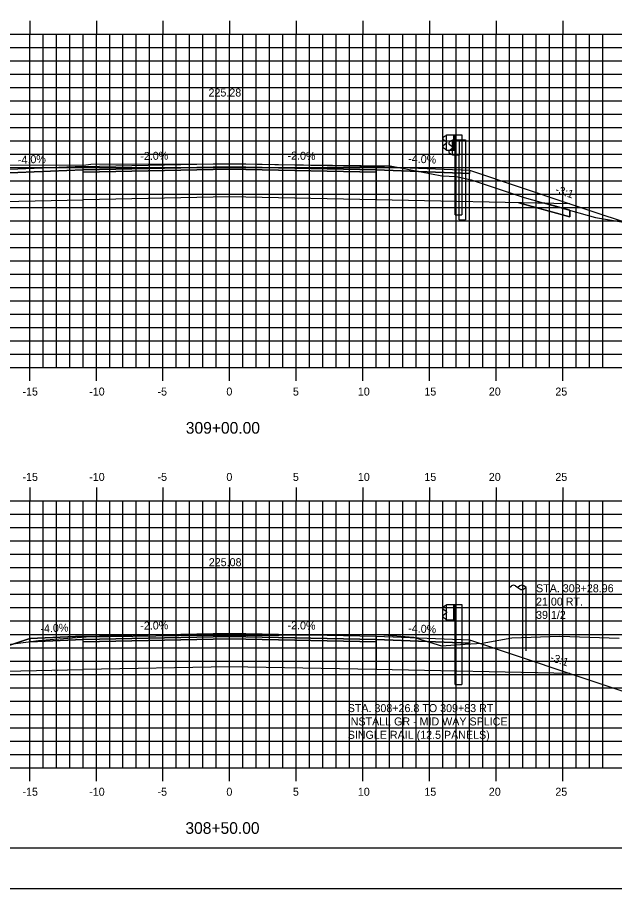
# Model space of a CAD drawing. Extents: x 1137876 to 1138046, y 608981 to 609091.
# Drawn here: x 1137943.2 to 1137988.1, y 608981.3 to 609046.6 of the extents above; entities that cross this region are included whole.
import ezdxf

# ---------------------------------------------------------------- set-up
doc = ezdxf.new("R2010")
doc.units = 0
for name, color, linetype in [('ANNOTATION', 7, 'Continuous'), ('BORDER', 7, 'Continuous'), ('D_Guardrail_Beam_Lt', 7, 'Continuous'), ('D_Guardrail_Beam_Rt', 7, 'Continuous'), ('D_Roadway_Centerline', 7, 'Continuous'), ('D_Roadway_Centerline_Text', 7, 'Continuous'), ('D_Roadway_Edge_Shoulder', 7, 'Continuous'), ('D_Roadway_Edge_TW', 7, 'Continuous'), ('D_Roadway_Pavement', 7, 'Continuous'), ('D_Roadway_SlopeLines', 7, 'Continuous'), ('D_Roadway_SubGrade', 7, 'Continuous'), ('D_Text_Standard', 7, 'Continuous'), ('D_Utilities_Pole_Joint_Rt', 7, 'Continuous'), ('H_V ANNOTATION', 7, 'Continuous'), ('MAJOR', 7, 'Continuous'), ('MINOR', 7, 'Continuous'), ('PLOT BOUNDARY', 7, 'Continuous'), ('S_Guardrail_Beam', 7, 'Continuous'), ('S_Roadway_Centerline', 7, 'Continuous'), ('SHADING', 7, 'Continuous')]:
    doc.layers.add(name, color=color, linetype=linetype)

msp = doc.modelspace()

# ---------------------------------------------------------------- linework, layer by layer
msp.add_lwpolyline([(1137920.838, 609001.638), (1137922.088, 609001.503), (1137923.338, 609001.228), (1137924.588, 609000.813), (1137925.838, 609000.258), (1137933.441, 608996.457), (1137936.441, 608997.457), (1137944.165, 609000.031), (1137944.166, 609000.031), (1137948.166, 609000.191), (1137959.166, 609000.411), (1137970.166, 609000.191), (1137977.166, 608999.911), (1137984.698, 608997.4), (1137989.882, 608995.673), (1137996.551, 608999.007), (1137997.801, 608999.558), (1137999.051, 608999.962), (1138000.301, 609000.217), (1138001.551, 609000.325)])
at = {"layer": 'BORDER'}
msp.add_lwpolyline([(1137884.166, 608984.335), (1138044.166, 608984.335), (1138044.166, 609089.335), (1137884.166, 609089.335)], close=True, dxfattribs=at)
at = {"layer": 'D_Guardrail_Beam_Lt'}
for p, q in [((1137975.347, 609037.679), (1137975.203, 609037.579)), ((1137975.437, 609037.7), (1137975.363, 609037.685)), ((1137975.203, 609037.436), (1137975.399, 609037.3)), ((1137975.399, 609037.101), (1137975.203, 609036.964)), ((1137975.203, 609036.821), (1137975.347, 609036.721)), ((1137975.432, 609037.235), (1137975.432, 609037.165)), ((1137975.363, 609036.715), (1137975.437, 609036.7)), ((1137975.347, 609002.47), (1137975.203, 609002.37)), ((1137975.203, 609002.227), (1137975.399, 609002.091)), ((1137975.437, 609002.491), (1137975.363, 609002.477)), ((1137975.399, 609001.892), (1137975.203, 609001.755)), ((1137975.203, 609001.612), (1137975.347, 609001.512)), ((1137975.432, 609002.026), (1137975.432, 609001.956)), ((1137975.363, 609001.506), (1137975.437, 609001.491))]:
    msp.add_line(p, q, dxfattribs=at)
for centre, major_axis, start_param, end_param in [((1137975.254, 609037.507), (-0.0877, 0), 5.323254, 7.243116), ((1137975.371, 609037.645), (-0.0417, 0), 4.907132, 5.323254), ((1137975.254, 609036.893), (-0.0877, 0), 5.323254, 7.243116), ((1137975.353, 609037.235), (0.0789, 0), 0, 0.959931), ((1137975.353, 609037.165), (0.0789, 0), 5.323254, 6.283185), ((1137975.371, 609036.755), (-0.0417, 0), 0.959931, 1.376053), ((1137975.254, 609002.298), (-0.0877, 0), 5.323254, 7.243116), ((1137975.371, 609002.436), (-0.0417, 0), 4.907132, 5.323254), ((1137975.254, 609001.684), (-0.0877, 0), 5.323254, 7.243116), ((1137975.353, 609002.026), (0.0789, 0), 0, 0.959931), ((1137975.353, 609001.956), (0.0789, 0), 5.323254, 6.283185), ((1137975.371, 609001.546), (-0.0417, 0), 0.959931, 1.376053)]:
    msp.add_ellipse(centre, major_axis=major_axis, ratio=0.995501, start_param=start_param, end_param=end_param, dxfattribs=at)
at = {"layer": 'D_Guardrail_Beam_Rt'}
for p, q in [((1137975.437, 609037.783), (1137976.124, 609037.783)), ((1137975.437, 609036.617), (1137975.437, 609037.783)), ((1137975.958, 609037.783), (1137975.958, 609036.617)), ((1137976.062, 609037.783), (1137976.062, 609036.617)), ((1137976.124, 609037.783), (1137976.595, 609037.783)), ((1137976.124, 609037.783), (1137976.124, 609036.617)), ((1137976.595, 609037.783), (1137976.595, 609031.783)), ((1137976.124, 609036.617), (1137975.437, 609036.617)), ((1137976.103, 609031.783), (1137976.103, 609036.617)), ((1137976.103, 609031.783), (1137976.595, 609031.783)), ((1137975.437, 609002.574), (1137976.124, 609002.574)), ((1137975.437, 609001.408), (1137975.437, 609002.574)), ((1137975.958, 609002.574), (1137975.958, 609001.408)), ((1137976.062, 609002.574), (1137976.062, 609001.408)), ((1137976.124, 609002.574), (1137976.595, 609002.574)), ((1137976.124, 609002.574), (1137976.124, 609001.408)), ((1137976.595, 609002.574), (1137976.595, 608996.574)), ((1137976.124, 609001.408), (1137975.437, 609001.408)), ((1137976.103, 608996.574), (1137976.103, 609001.408)), ((1137976.103, 608996.574), (1137976.595, 608996.574))]:
    msp.add_line(p, q, dxfattribs=at)
at = {"layer": 'D_Roadway_Edge_Shoulder'}
for points in [[(1137948.166, 609035.4), (1137940.788, 609035.105), (1137940.788, 609034.855), (1137948.166, 609035.15)], [(1137970.166, 609035.4), (1137977.166, 609035.12), (1137977.166, 609034.87), (1137970.166, 609035.15)], [(1137948.166, 609000.191), (1137944.166, 609000.031), (1137944.166, 608999.781), (1137948.166, 608999.941)], [(1137970.166, 609000.191), (1137977.166, 608999.911), (1137977.166, 608999.661), (1137970.166, 608999.941)]]:
    msp.add_lwpolyline(points, close=True, dxfattribs=at)
at = {"layer": 'D_Roadway_Edge_TW'}
for points in [[(1137948.166, 609035.15), (1137948.166, 609035.4), (1137959.166, 609035.62), (1137970.166, 609035.4), (1137970.166, 609035.15), (1137959.166, 609035.37)], [(1137948.166, 608999.941), (1137948.166, 609000.191), (1137959.166, 609000.411), (1137970.166, 609000.191), (1137970.166, 608999.941), (1137959.166, 609000.161)]]:
    msp.add_lwpolyline(points, close=True, dxfattribs=at)
at = {"layer": 'D_Roadway_Pavement'}
for points in [[(1137948.166, 609034.983), (1137948.166, 609035.15), (1137959.166, 609035.37), (1137970.166, 609035.15), (1137970.166, 609034.983), (1137959.166, 609035.203)], [(1137948.166, 608999.774), (1137948.166, 608999.941), (1137959.166, 609000.161), (1137970.166, 608999.941), (1137970.166, 608999.774), (1137959.166, 608999.994)]]:
    msp.add_lwpolyline(points, close=True, dxfattribs=at)
at = {"layer": 'D_Roadway_SlopeLines'}
for points in [[(1137984.698, 609032.125), (1137984.698, 609031.625), (1137980.875, 609032.686)], [(1137984.698, 609032.609), (1137990.642, 609030.628)], [(1137984.698, 608997.4), (1137989.882, 608995.673)]]:
    msp.add_lwpolyline(points, dxfattribs=at)
at = {"layer": 'D_Roadway_SubGrade'}
msp.add_lwpolyline([(1137939.722, 609032.731), (1137948.166, 609032.9), (1137948.166, 609034.983), (1137948.166, 609035.15), (1137940.788, 609034.855), (1137940.788, 609035.105), (1137940.787, 609035.105), (1137940.787, 609035.105)], dxfattribs=at)
for points in [[(1137948.166, 609032.9), (1137948.166, 609034.983), (1137959.166, 609035.203), (1137970.166, 609034.983), (1137970.166, 609032.9), (1137959.166, 609033.12)], [(1137970.166, 609034.983), (1137970.166, 609035.15), (1137977.166, 609034.87), (1137977.166, 609035.12), (1137977.166, 609035.12), (1137984.698, 609032.609), (1137970.166, 609032.9)], [(1137948.166, 608999.774), (1137948.166, 608999.941), (1137944.166, 608999.781), (1137944.166, 609000.031), (1137944.165, 609000.031), (1137936.441, 608997.457), (1137948.166, 608997.691)], [(1137948.166, 608997.691), (1137948.166, 608999.774), (1137959.166, 608999.994), (1137970.166, 608999.774), (1137970.166, 608997.691), (1137959.166, 608997.911)], [(1137970.166, 608999.774), (1137970.166, 608999.941), (1137977.166, 608999.661), (1137977.166, 608999.911), (1137977.166, 608999.911), (1137984.698, 608997.4), (1137970.166, 608997.691)]]:
    msp.add_lwpolyline(points, close=True, dxfattribs=at)
at = {"layer": 'D_Utilities_Pole_Joint_Rt'}
for p, q in [((1137980.164, 609003.85), (1137980.32, 609003.961)), ((1137980.164, 608999.092), (1137980.164, 609003.85)), ((1137980.632, 609003.961), (1137980.789, 609003.85)), ((1137980.945, 609003.961), (1137980.789, 609003.85)), ((1137980.789, 609003.85), (1137980.945, 609003.739)), ((1137981.414, 609003.85), (1137981.258, 609003.961)), ((1137981.258, 609003.739), (1137981.414, 609003.85)), ((1137981.414, 608999.092), (1137981.414, 609003.85))]:
    msp.add_line(p, q, dxfattribs=at)
for centre, start, end in [((1137980.476, 609003.74), 90, 125.26439), ((1137980.476, 609003.74), 54.73561, 90), ((1137981.101, 609003.74), 90, 125.26439), ((1137981.101, 609003.961), 234.73561, 270), ((1137981.101, 609003.74), 54.73561, 90), ((1137981.101, 609003.961), 270, 305.26439)]:
    msp.add_arc(centre, 0.271, start, end, dxfattribs=at)
at = {"layer": 'MAJOR'}
for p, q in [((1137944.166, 609046.337), (1137944.166, 609045.335)), ((1137949.166, 609046.337), (1137949.166, 609045.335)), ((1137954.166, 609046.337), (1137954.166, 609045.335)), ((1137959.166, 609046.337), (1137959.166, 609045.335)), ((1137964.166, 609046.337), (1137964.166, 609045.335)), ((1137969.166, 609046.337), (1137969.166, 609045.335)), ((1137974.166, 609046.337), (1137974.166, 609045.335)), ((1137979.166, 609046.337), (1137979.166, 609045.335)), ((1137984.166, 609046.337), (1137984.166, 609045.335)), ((1137889.166, 609045.335), (1138029.166, 609045.335)), ((1137889.166, 609045.335), (1138029.166, 609045.335)), ((1137944.166, 609020.335), (1137944.166, 609045.335)), ((1137949.166, 609020.335), (1137949.166, 609045.335)), ((1137954.166, 609020.335), (1137954.166, 609045.335)), ((1137959.166, 609020.335), (1137959.166, 609045.335)), ((1137964.166, 609020.335), (1137964.166, 609045.335)), ((1137969.166, 609020.335), (1137969.166, 609045.335)), ((1137974.166, 609020.335), (1137974.166, 609045.335)), ((1137979.166, 609020.335), (1137979.166, 609045.335)), ((1137984.166, 609020.335), (1137984.166, 609045.335)), ((1137889.166, 609040.335), (1138029.166, 609040.335)), ((1137889.166, 609035.335), (1138029.166, 609035.335)), ((1137889.166, 609030.335), (1138029.166, 609030.335)), ((1137889.166, 609025.335), (1138029.166, 609025.335)), ((1137889.166, 609020.335), (1138029.166, 609020.335)), ((1137889.166, 609020.335), (1138029.166, 609020.335)), ((1137944.166, 609019.333), (1137944.166, 609020.335)), ((1137949.166, 609019.333), (1137949.166, 609020.335)), ((1137954.166, 609019.333), (1137954.166, 609020.335)), ((1137959.166, 609019.333), (1137959.166, 609020.335)), ((1137964.166, 609019.333), (1137964.166, 609020.335)), ((1137969.166, 609019.333), (1137969.166, 609020.335)), ((1137974.166, 609019.333), (1137974.166, 609020.335)), ((1137979.166, 609019.333), (1137979.166, 609020.335)), ((1137984.166, 609019.333), (1137984.166, 609020.335)), ((1137944.166, 609011.337), (1137944.166, 609010.335)), ((1137949.166, 609011.337), (1137949.166, 609010.335)), ((1137954.166, 609011.337), (1137954.166, 609010.335)), ((1137959.166, 609011.337), (1137959.166, 609010.335)), ((1137964.166, 609011.337), (1137964.166, 609010.335)), ((1137969.166, 609011.337), (1137969.166, 609010.335)), ((1137974.166, 609011.337), (1137974.166, 609010.335)), ((1137979.166, 609011.337), (1137979.166, 609010.335)), ((1137984.166, 609011.337), (1137984.166, 609010.335)), ((1137889.166, 609010.335), (1138029.166, 609010.335)), ((1137889.166, 609010.335), (1138029.166, 609010.335)), ((1137944.166, 608990.335), (1137944.166, 609010.335)), ((1137949.166, 608990.335), (1137949.166, 609010.335)), ((1137954.166, 608990.335), (1137954.166, 609010.335)), ((1137959.166, 608990.335), (1137959.166, 609010.335)), ((1137964.166, 608990.335), (1137964.166, 609010.335)), ((1137969.166, 608990.335), (1137969.166, 609010.335)), ((1137974.166, 608990.335), (1137974.166, 609010.335)), ((1137979.166, 608990.335), (1137979.166, 609010.335)), ((1137984.166, 608990.335), (1137984.166, 609010.335)), ((1137889.166, 609005.335), (1138029.166, 609005.335)), ((1137889.166, 609000.335), (1138029.166, 609000.335)), ((1137889.166, 608995.335), (1138029.166, 608995.335)), ((1137889.166, 608990.335), (1138029.166, 608990.335)), ((1137889.166, 608990.335), (1138029.166, 608990.335)), ((1137944.166, 608989.333), (1137944.166, 608990.335)), ((1137949.166, 608989.333), (1137949.166, 608990.335)), ((1137954.166, 608989.333), (1137954.166, 608990.335)), ((1137959.166, 608989.333), (1137959.166, 608990.335)), ((1137964.166, 608989.333), (1137964.166, 608990.335)), ((1137969.166, 608989.333), (1137969.166, 608990.335)), ((1137974.166, 608989.333), (1137974.166, 608990.335)), ((1137979.166, 608989.333), (1137979.166, 608990.335)), ((1137984.166, 608989.333), (1137984.166, 608990.335))]:
    msp.add_line(p, q, dxfattribs=at)
at = {"layer": 'MINOR'}
for p, q in [((1137945.166, 609020.335), (1137945.166, 609045.335)), ((1137946.166, 609020.335), (1137946.166, 609045.335)), ((1137947.166, 609020.335), (1137947.166, 609045.335)), ((1137948.166, 609020.335), (1137948.166, 609045.335)), ((1137950.166, 609020.335), (1137950.166, 609045.335)), ((1137951.166, 609020.335), (1137951.166, 609045.335)), ((1137952.166, 609020.335), (1137952.166, 609045.335)), ((1137953.166, 609020.335), (1137953.166, 609045.335)), ((1137955.166, 609020.335), (1137955.166, 609045.335)), ((1137956.166, 609020.335), (1137956.166, 609045.335)), ((1137957.166, 609020.335), (1137957.166, 609045.335)), ((1137958.166, 609020.335), (1137958.166, 609045.335)), ((1137960.166, 609020.335), (1137960.166, 609045.335)), ((1137961.166, 609020.335), (1137961.166, 609045.335)), ((1137962.166, 609020.335), (1137962.166, 609045.335)), ((1137963.166, 609020.335), (1137963.166, 609045.335)), ((1137965.166, 609020.335), (1137965.166, 609045.335)), ((1137966.166, 609020.335), (1137966.166, 609045.335)), ((1137967.166, 609020.335), (1137967.166, 609045.335)), ((1137968.166, 609020.335), (1137968.166, 609045.335)), ((1137970.166, 609020.335), (1137970.166, 609045.335)), ((1137971.166, 609020.335), (1137971.166, 609045.335)), ((1137972.166, 609020.335), (1137972.166, 609045.335)), ((1137973.166, 609020.335), (1137973.166, 609045.335)), ((1137975.166, 609020.335), (1137975.166, 609045.335)), ((1137976.166, 609020.335), (1137976.166, 609045.335)), ((1137977.166, 609020.335), (1137977.166, 609045.335)), ((1137978.166, 609020.335), (1137978.166, 609045.335)), ((1137980.166, 609020.335), (1137980.166, 609045.335)), ((1137981.166, 609020.335), (1137981.166, 609045.335)), ((1137982.166, 609020.335), (1137982.166, 609045.335)), ((1137983.166, 609020.335), (1137983.166, 609045.335)), ((1137985.166, 609020.335), (1137985.166, 609045.335)), ((1137986.166, 609020.335), (1137986.166, 609045.335)), ((1137987.166, 609020.335), (1137987.166, 609045.335)), ((1137889.166, 609044.335), (1138029.166, 609044.335)), ((1137889.166, 609043.335), (1138029.166, 609043.335)), ((1137889.166, 609042.335), (1138029.166, 609042.335)), ((1137889.166, 609041.335), (1138029.166, 609041.335)), ((1137889.166, 609039.335), (1138029.166, 609039.335)), ((1137889.166, 609038.335), (1138029.166, 609038.335)), ((1137889.166, 609037.335), (1138029.166, 609037.335)), ((1137889.166, 609036.335), (1138029.166, 609036.335)), ((1137889.166, 609034.335), (1138029.166, 609034.335)), ((1137889.166, 609033.335), (1138029.166, 609033.335)), ((1137889.166, 609032.335), (1138029.166, 609032.335)), ((1137889.166, 609031.335), (1138029.166, 609031.335)), ((1137889.166, 609029.335), (1138029.166, 609029.335)), ((1137889.166, 609028.335), (1138029.166, 609028.335)), ((1137889.166, 609027.335), (1138029.166, 609027.335)), ((1137889.166, 609026.335), (1138029.166, 609026.335)), ((1137889.166, 609024.335), (1138029.166, 609024.335)), ((1137889.166, 609023.335), (1138029.166, 609023.335)), ((1137889.166, 609022.335), (1138029.166, 609022.335)), ((1137889.166, 609021.335), (1138029.166, 609021.335)), ((1137945.166, 608990.335), (1137945.166, 609010.335)), ((1137946.166, 608990.335), (1137946.166, 609010.335)), ((1137947.166, 608990.335), (1137947.166, 609010.335)), ((1137948.166, 608990.335), (1137948.166, 609010.335)), ((1137950.166, 608990.335), (1137950.166, 609010.335)), ((1137951.166, 608990.335), (1137951.166, 609010.335)), ((1137952.166, 608990.335), (1137952.166, 609010.335)), ((1137953.166, 608990.335), (1137953.166, 609010.335)), ((1137955.166, 608990.335), (1137955.166, 609010.335)), ((1137956.166, 608990.335), (1137956.166, 609010.335)), ((1137957.166, 608990.335), (1137957.166, 609010.335)), ((1137958.166, 608990.335), (1137958.166, 609010.335)), ((1137960.166, 608990.335), (1137960.166, 609010.335)), ((1137961.166, 608990.335), (1137961.166, 609010.335)), ((1137962.166, 608990.335), (1137962.166, 609010.335)), ((1137963.166, 608990.335), (1137963.166, 609010.335)), ((1137965.166, 608990.335), (1137965.166, 609010.335)), ((1137966.166, 608990.335), (1137966.166, 609010.335)), ((1137967.166, 608990.335), (1137967.166, 609010.335)), ((1137968.166, 608990.335), (1137968.166, 609010.335)), ((1137970.166, 608990.335), (1137970.166, 609010.335)), ((1137971.166, 608990.335), (1137971.166, 609010.335)), ((1137972.166, 608990.335), (1137972.166, 609010.335)), ((1137973.166, 608990.335), (1137973.166, 609010.335)), ((1137975.166, 608990.335), (1137975.166, 609010.335)), ((1137976.166, 608990.335), (1137976.166, 609010.335)), ((1137977.166, 608990.335), (1137977.166, 609010.335)), ((1137978.166, 608990.335), (1137978.166, 609010.335)), ((1137980.166, 608990.335), (1137980.166, 609010.335)), ((1137981.166, 608990.335), (1137981.166, 609010.335)), ((1137982.166, 608990.335), (1137982.166, 609010.335)), ((1137983.166, 608990.335), (1137983.166, 609010.335)), ((1137985.166, 608990.335), (1137985.166, 609010.335)), ((1137986.166, 608990.335), (1137986.166, 609010.335)), ((1137987.166, 608990.335), (1137987.166, 609010.335)), ((1137889.166, 609009.335), (1138029.166, 609009.335)), ((1137889.166, 609008.335), (1138029.166, 609008.335)), ((1137889.166, 609007.335), (1138029.166, 609007.335)), ((1137889.166, 609006.335), (1138029.166, 609006.335)), ((1137889.166, 609004.335), (1138029.166, 609004.335)), ((1137889.166, 609003.335), (1138029.166, 609003.335)), ((1137889.166, 609002.335), (1138029.166, 609002.335)), ((1137889.166, 609001.335), (1138029.166, 609001.335)), ((1137889.166, 608999.335), (1138029.166, 608999.335)), ((1137889.166, 608998.335), (1138029.166, 608998.335)), ((1137889.166, 608997.335), (1138029.166, 608997.335)), ((1137889.166, 608996.335), (1138029.166, 608996.335)), ((1137889.166, 608994.335), (1138029.166, 608994.335)), ((1137889.166, 608993.335), (1138029.166, 608993.335)), ((1137889.166, 608992.335), (1138029.166, 608992.335)), ((1137889.166, 608991.335), (1138029.166, 608991.335))]:
    msp.add_line(p, q, dxfattribs=at)
at = {"layer": 'PLOT BOUNDARY'}
msp.add_lwpolyline([(1137876.073, 608981.276), (1138046.073, 608981.276), (1138046.073, 609091.276), (1137876.073, 609091.276)], close=True, dxfattribs=at)
at = {"layer": 'S_Guardrail_Beam'}
for p, q in [((1137975.797, 609037.318), (1137975.653, 609037.218)), ((1137975.653, 609037.075), (1137975.849, 609036.939)), ((1137975.895, 609037.339), (1137975.813, 609037.325)), ((1137975.882, 609036.874), (1137975.882, 609036.783)), ((1137975.895, 609037.412), (1137976.385, 609037.412)), ((1137975.895, 609036.245), (1137975.895, 609037.412)), ((1137976.385, 609037.412), (1137976.877, 609037.412)), ((1137976.385, 609037.412), (1137976.385, 609036.245)), ((1137976.877, 609037.412), (1137976.877, 609031.412)), ((1137975.849, 609036.719), (1137975.653, 609036.583)), ((1137975.653, 609036.439), (1137975.797, 609036.34)), ((1137975.813, 609036.333), (1137975.895, 609036.318)), ((1137976.385, 609036.245), (1137975.895, 609036.245)), ((1137976.385, 609031.412), (1137976.385, 609036.245)), ((1137976.385, 609031.412), (1137976.877, 609031.412))]:
    msp.add_line(p, q, dxfattribs=at)
for centre, major_axis, start_param, end_param in [((1137975.703, 609037.146), (-0.0877, 0), 5.323254, 7.243116), ((1137975.821, 609037.284), (-0.0417, 0), 4.886922, 5.323254), ((1137975.803, 609036.874), (0.0789, 0), 0, 0.959931), ((1137975.703, 609036.511), (-0.0877, 0), 5.323254, 7.243116), ((1137975.821, 609036.373), (-0.0417, 0), 0.959931, 1.396263), ((1137975.803, 609036.783), (0.0789, 0), 5.323254, 6.283185)]:
    msp.add_ellipse(centre, major_axis=major_axis, ratio=0.995501, start_param=start_param, end_param=end_param, dxfattribs=at)
at = {"layer": 'S_Roadway_Centerline'}
for points in [[(1137889.166, 609035.87), (1137897.769, 609036.097), (1137903.847, 609036.195), (1137922.362, 609036.192), (1137923.647, 609036.227), (1137923.926, 609036.236), (1137941.45, 609035.497), (1137942.404, 609035.527), (1137948.191, 609035.512), (1137948.754, 609035.58), (1137958.379, 609035.602), (1137959.886, 609035.609), (1137962.573, 609035.562), (1137971.217, 609035.463), (1137975.089, 609034.703), (1137976.201, 609034.668), (1137977.29, 609034.412), (1137981.28, 609033.073), (1137986.631, 609031.589), (1137994.165, 609030.324)], [(1137913.402, 609002.025), (1137925.071, 609001.418), (1137925.992, 609001.418), (1137929.134, 609000.907), (1137938.63, 608999.416), (1137939.85, 608999.214), (1137944.822, 608999.879), (1137945.703, 608999.951), (1137945.946, 608999.984), (1137946.358, 608999.993), (1137948.391, 609000.159), (1137957.12, 609000.265), (1137958.769, 609000.269), (1137960.476, 609000.25), (1137970.117, 609000.341), (1137972.353, 609000.179), (1137972.977, 609000.115), (1137973.526, 608999.958), (1137975.073, 608999.475), (1137976.852, 608999.609), (1137978.118, 608999.683), (1137980.358, 609000.082), (1137983.958, 609000.205), (1137988.409, 609000.056)]]:
    msp.add_lwpolyline(points, dxfattribs=at)
at = {"layer": 'SHADING'}
for p, q in [((1137982.817, 609032.647), (1137980.875, 609032.686)), ((1137984.698, 609032.125), (1137982.817, 609032.647))]:
    msp.add_line(p, q, dxfattribs=at)
msp.add_lwpolyline([(1137980.875, 609032.686), (1137984.698, 609031.625), (1137984.698, 609032.125)], dxfattribs=at)

# ---------------------------------------------------------------- texts
at = {"layer": 'ANNOTATION'}
for s, rotation, p in [('-4.0%', 2.29061, (1137943.293, 609035.606)), ('-2.0%', 1.14576, (1137952.469, 609035.886)), ('-2.0%', 358.85424, (1137963.509, 609035.933)), ('-4.0%', 357.70939, (1137972.562, 609035.705)), ('-3:1', 341.56517, (1137983.553, 609033.445)), ('-4.0%', 2.29061, (1137944.982, 609000.465)), ('-2.0%', 1.14576, (1137952.469, 609000.677)), ('-2.0%', 358.85424, (1137963.509, 609000.724)), ('-4.0%', 357.70939, (1137972.562, 609000.496)), ('-3:1', 341.56519, (1137983.174, 608998.363))]:
    msp.add_text(s, height=0.6, rotation=rotation, dxfattribs=at).set_placement(p)
for s, p in [('STA. 308+26.8 TO 309+83 RT', (1137968.031, 608994.506)), ('INSTALL GR - MID WAY SPLICE', (1137968.031, 608993.504)), ('SINGLE RAIL (12.5 PANELS)', (1137968.031, 608992.502))]:
    msp.add_text(s, height=0.6, dxfattribs=at).set_placement(p)
at = {"layer": 'D_Roadway_Centerline'}
for s, p in [('C', (1137959.161, 609035.62)), ('L', (1137959.166, 609035.613)), ('C', (1137959.161, 609000.411)), ('L', (1137959.166, 609000.404))]:
    msp.add_text(s, height=0.0146, dxfattribs=at).set_placement(p)
at = {"layer": 'D_Roadway_Centerline_Text'}
for s, p in [('225.28', (1137957.585, 609040.652)), ('225.08', (1137957.606, 609005.443))]:
    msp.add_text(s, height=0.6, dxfattribs=at).set_placement(p)
at = {"layer": 'D_Text_Standard'}
for s, p in [('STA. 308+28.96', (1137982.164, 609003.49)), ('21.00 RT.', (1137982.164, 609002.488)), ('39 1/2 ', (1137982.164, 609001.492))]:
    msp.add_text(s, height=0.6, dxfattribs=at).set_placement(p)
at = {"layer": 'H_V ANNOTATION'}
for s, height, p in [('-15', 0.6, (1137943.623, 609018.235)), ('-10', 0.6, (1137948.631, 609018.235)), ('-5', 0.6, (1137953.757, 609018.235)), ('0', 0.6, (1137958.925, 609018.235)), ('5', 0.6, (1137963.917, 609018.235)), ('10', 0.6, (1137968.791, 609018.235)), ('15', 0.6, (1137973.783, 609018.235)), ('20', 0.6, (1137978.62, 609018.235)), ('25', 0.6, (1137983.612, 609018.235)), ('309+00.00', 0.875, (1137955.881, 609015.378)), ('-15', 0.6, (1137943.623, 609011.835)), ('-10', 0.6, (1137948.631, 609011.835)), ('-5', 0.6, (1137953.757, 609011.835)), ('0', 0.6, (1137958.925, 609011.835)), ('5', 0.6, (1137963.917, 609011.835)), ('10', 0.6, (1137968.791, 609011.835)), ('15', 0.6, (1137973.783, 609011.835)), ('20', 0.6, (1137978.62, 609011.835)), ('25', 0.6, (1137983.612, 609011.835)), ('-15', 0.6, (1137943.623, 608988.235)), ('-10', 0.6, (1137948.631, 608988.235)), ('-5', 0.6, (1137953.757, 608988.235)), ('0', 0.6, (1137958.925, 608988.235)), ('5', 0.6, (1137963.917, 608988.235)), ('10', 0.6, (1137968.791, 608988.235)), ('15', 0.6, (1137973.783, 608988.235)), ('20', 0.6, (1137978.62, 608988.235)), ('25', 0.6, (1137983.612, 608988.235)), ('308+50.00', 0.875, (1137955.85, 608985.378))]:
    msp.add_text(s, height=height, dxfattribs=at).set_placement(p)
at = {"layer": 'S_Roadway_Centerline'}
for s, p in [('C', (1137959.881, 609035.609)), ('L', (1137959.886, 609035.602)), ('L', (1137958.761, 609000.261)), ('C', (1137958.764, 609000.269))]:
    msp.add_text(s, height=0.0146, dxfattribs=at).set_placement(p)

doc.saveas('drawing.dxf')
